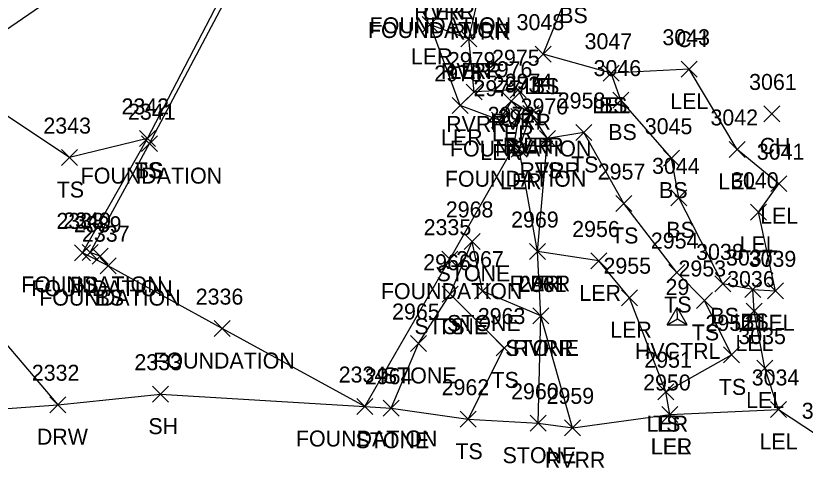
# Model space of a CAD drawing. Extents: x 1512665 to 1513714, y 110636 to 112816.
# Drawn here: x 1513001.7 to 1513100.4, y 110641.4 to 110699.2 of the extents above; entities that cross this region are included whole.
import ezdxf

# ---------------------------------------------------------------- set-up
doc = ezdxf.new("R2010")
doc.units = 0
for name, color, linetype in [('C_A', 7, 'Continuous'), ('C_I', 7, 'Continuous'), ('CPSM', 7, 'Continuous'), ('L_A', 7, 'Continuous'), ('L_I', 7, 'Continuous'), ('L_TIC', 7, 'Continuous'), ('LARO', 7, 'Continuous'), ('LASF', 7, 'Continuous'), ('LAWE', 7, 'Continuous'), ('LBC', 7, 'Continuous'), ('LELB', 7, 'Continuous'), ('LSOGP', 7, 'Continuous'), ('R_A', 7, 'Continuous'), ('R_I', 7, 'Continuous'), ('R_TIC', 7, 'Continuous'), ('RDW', 7, 'Continuous')]:
    doc.layers.add(name, color=color, linetype=linetype)

msp = doc.modelspace()

# ---------------------------------------------------------------- linework, layer by layer
at = {"layer": 'CPSM'}
for p, q in [((1513083.124, 110660.523), (1513084.374, 110662.688)), ((1513085.624, 110660.523), (1513084.374, 110662.688)), ((1513084.375, 110661.244), (1513084.374, 110662.688)), ((1513083.124, 110660.523), (1513084.375, 110661.244)), ((1513084.375, 110661.244), (1513084.375, 110661.244)), ((1513084.375, 110661.244), (1513085.624, 110660.523)), ((1513083.124, 110660.523), (1513085.624, 110660.523))]:
    msp.add_line(p, q, dxfattribs=at)
at = {"layer": 'L_TIC'}
for points in [[(1513052.488, 110697.104), (1513054.488, 110699.104)], [(1513054.488, 110697.104), (1513052.488, 110699.104)], [(1513057.313, 110695.292), (1513059.313, 110697.292)], [(1513059.313, 110695.292), (1513057.313, 110697.292)], [(1513057.313, 110695.292), (1513059.313, 110697.292)], [(1513059.313, 110695.292), (1513057.313, 110697.292)], [(1513066.62, 110693.387), (1513068.62, 110695.387)], [(1513068.62, 110693.387), (1513066.62, 110695.387)], [(1513066.62, 110693.387), (1513068.62, 110695.387)], [(1513068.62, 110693.387), (1513066.62, 110695.387)], [(1513084.847, 110691.498), (1513086.847, 110693.498)], [(1513086.847, 110691.498), (1513084.847, 110693.498)], [(1513075.12, 110690.994), (1513077.12, 110692.994)], [(1513077.12, 110690.994), (1513075.12, 110692.994)], [(1513075.12, 110690.994), (1513077.12, 110692.994)], [(1513077.12, 110690.994), (1513075.12, 110692.994)], [(1513057.96, 110688.646), (1513059.96, 110690.646)], [(1513059.96, 110688.646), (1513057.96, 110690.646)], [(1513063.476, 110688.933), (1513065.476, 110690.933)], [(1513065.476, 110688.933), (1513063.476, 110690.933)], [(1513076.298, 110687.636), (1513078.298, 110689.636)], [(1513078.298, 110687.636), (1513076.298, 110689.636)], [(1513056.248, 110686.974), (1513058.248, 110688.974)], [(1513058.248, 110686.974), (1513056.248, 110688.974)], [(1513062.621, 110687.488), (1513064.621, 110689.488)], [(1513064.621, 110687.488), (1513062.621, 110689.488)], [(1513063.556, 110685.576), (1513065.556, 110687.576)], [(1513065.556, 110685.576), (1513063.556, 110687.576)], [(1513065.06, 110685.938), (1513067.06, 110687.938)], [(1513067.06, 110685.938), (1513065.06, 110687.938)], [(1513065.06, 110685.938), (1513067.06, 110687.938)], [(1513067.06, 110685.938), (1513065.06, 110687.938)], [(1513095.167, 110685.902), (1513097.167, 110687.902)], [(1513097.167, 110685.902), (1513095.167, 110687.902)], [(1513061.15, 110685.123), (1513063.15, 110687.123)], [(1513063.15, 110685.123), (1513061.15, 110687.123)], [(1513071.687, 110683.582), (1513073.687, 110685.582)], [(1513073.687, 110683.582), (1513071.687, 110685.582)], [(1513017.15, 110682.845), (1513019.15, 110684.845)], [(1513019.15, 110682.845), (1513017.15, 110684.845)], [(1513017.15, 110682.845), (1513019.15, 110684.845)], [(1513019.15, 110682.845), (1513017.15, 110684.845)], [(1513067.127, 110682.845), (1513069.127, 110684.845)], [(1513069.127, 110682.845), (1513067.127, 110684.845)], [(1513067.127, 110682.845), (1513069.127, 110684.845)], [(1513069.127, 110682.845), (1513067.127, 110684.845)], [(1513017.401, 110682.181), (1513019.401, 110684.181)], [(1513019.401, 110682.181), (1513017.401, 110684.181)], [(1513062.919, 110681.793), (1513064.919, 110683.793)], [(1513064.919, 110681.793), (1513062.919, 110683.793)], [(1513063.621, 110681.479), (1513065.621, 110683.479)], [(1513065.621, 110681.479), (1513063.621, 110683.479)], [(1513090.854, 110681.46), (1513092.854, 110683.46)], [(1513092.854, 110681.46), (1513090.854, 110683.46)], [(1513007.389, 110680.438), (1513009.389, 110682.438)], [(1513009.389, 110680.438), (1513007.389, 110682.438)], [(1513082.646, 110680.369), (1513084.646, 110682.369)], [(1513084.646, 110680.369), (1513082.646, 110682.369)], [(1513096.083, 110677.175), (1513098.083, 110679.175)], [(1513098.083, 110677.175), (1513096.083, 110679.175)], [(1513076.687, 110674.691), (1513078.687, 110676.691)], [(1513078.687, 110674.691), (1513076.687, 110676.691)], [(1513083.558, 110675.404), (1513085.558, 110677.404)], [(1513085.558, 110675.404), (1513083.558, 110677.404)], [(1513093.517, 110673.6), (1513095.517, 110675.6)], [(1513095.517, 110673.6), (1513093.517, 110675.6)], [(1513057.739, 110669.956), (1513059.739, 110671.956)], [(1513059.739, 110669.956), (1513057.739, 110671.956)], [(1513057.739, 110669.956), (1513059.739, 110671.956)], [(1513059.739, 110669.956), (1513057.739, 110671.956)], [(1513009.024, 110668.518), (1513011.024, 110670.518)], [(1513011.024, 110668.518), (1513009.024, 110670.518)], [(1513009.961, 110668.569), (1513011.961, 110670.569)], [(1513011.961, 110668.569), (1513009.961, 110670.569)], [(1513011.214, 110668.098), (1513013.214, 110670.098)], [(1513013.214, 110668.098), (1513011.214, 110670.098)], [(1513065.91, 110668.682), (1513067.91, 110670.682)], [(1513067.91, 110668.682), (1513065.91, 110670.682)], [(1513065.91, 110668.682), (1513067.91, 110670.682)], [(1513067.91, 110668.682), (1513065.91, 110670.682)], [(1513012.218, 110666.913), (1513014.218, 110668.913)], [(1513014.218, 110666.913), (1513012.218, 110668.913)], [(1513012.218, 110666.913), (1513014.218, 110668.913)], [(1513014.218, 110666.913), (1513012.218, 110668.913)], [(1513054.923, 110667.727), (1513056.923, 110669.727)], [(1513056.923, 110667.727), (1513054.923, 110669.727)], [(1513073.543, 110667.504), (1513075.543, 110669.504)], [(1513075.543, 110667.504), (1513073.543, 110669.504)], [(1513083.328, 110666.051), (1513085.328, 110668.051)], [(1513085.328, 110666.051), (1513083.328, 110668.051)], [(1513089.065, 110664.64), (1513091.065, 110666.64)], [(1513091.065, 110664.64), (1513089.065, 110666.64)], [(1513092.793, 110663.924), (1513094.793, 110665.924)], [(1513094.793, 110663.924), (1513092.793, 110665.924)], [(1513092.793, 110663.924), (1513094.793, 110665.924)], [(1513094.793, 110663.924), (1513092.793, 110665.924)], [(1513054.973, 110663.335), (1513056.973, 110665.335)], [(1513056.973, 110663.335), (1513054.973, 110665.335)], [(1513054.973, 110663.335), (1513056.973, 110665.335)], [(1513056.973, 110663.335), (1513054.973, 110665.335)], [(1513059.041, 110663.737), (1513061.041, 110665.737)], [(1513061.041, 110663.737), (1513059.041, 110665.737)], [(1513077.4, 110662.905), (1513079.4, 110664.905)], [(1513079.4, 110662.905), (1513077.4, 110664.905)], [(1513095.64, 110663.766), (1513097.64, 110665.766)], [(1513097.64, 110663.766), (1513095.64, 110665.766)], [(1513086.78, 110662.565), (1513088.78, 110664.565)], [(1513088.78, 110662.565), (1513086.78, 110664.565)], [(1513092.997, 110661.241), (1513094.997, 110663.241)], [(1513094.997, 110661.241), (1513092.997, 110663.241)], [(1513066.32, 110660.62), (1513068.32, 110662.62)], [(1513068.32, 110660.62), (1513066.32, 110662.62)], [(1513066.32, 110660.62), (1513068.32, 110662.62)], [(1513068.32, 110660.62), (1513066.32, 110662.62)], [(1513026.487, 110659.038), (1513028.487, 110661.038)], [(1513028.487, 110659.038), (1513026.487, 110661.038)], [(1513051.026, 110657.175), (1513053.026, 110659.175)], [(1513053.026, 110657.175), (1513051.026, 110659.175)], [(1513061.741, 110656.612), (1513063.741, 110658.612)], [(1513063.741, 110656.612), (1513061.741, 110658.612)], [(1513090.152, 110655.745), (1513092.152, 110657.745)], [(1513092.152, 110655.745), (1513090.152, 110657.745)], [(1513094.331, 110654.098), (1513096.331, 110656.098)], [(1513096.331, 110654.098), (1513094.331, 110656.098)], [(1513081.939, 110651.144), (1513083.939, 110653.144)], [(1513083.939, 110651.144), (1513081.939, 110653.144)], [(1513081.939, 110651.144), (1513083.939, 110653.144)], [(1513083.939, 110651.144), (1513081.939, 110653.144)], [(1513018.765, 110650.834), (1513020.765, 110652.834)], [(1513020.765, 110650.834), (1513018.765, 110652.834)], [(1513044.304, 110649.287), (1513046.304, 110651.287)], [(1513046.304, 110649.287), (1513044.304, 110651.287)], [(1513044.304, 110649.287), (1513046.304, 110651.287)], [(1513046.304, 110649.287), (1513044.304, 110651.287)], [(1513047.61, 110649.075), (1513049.61, 110651.075)], [(1513049.61, 110649.075), (1513047.61, 110651.075)], [(1513082.446, 110648.297), (1513084.446, 110650.297)], [(1513084.446, 110648.297), (1513082.446, 110650.297)], [(1513082.446, 110648.297), (1513084.446, 110650.297)], [(1513084.446, 110648.297), (1513082.446, 110650.297)], [(1513096.009, 110648.923), (1513098.009, 110650.923)], [(1513098.009, 110648.923), (1513096.009, 110650.923)], [(1513057.22, 110647.703), (1513059.22, 110649.703)], [(1513059.22, 110647.703), (1513057.22, 110649.703)], [(1513065.989, 110647.2), (1513067.989, 110649.2)], [(1513067.989, 110647.2), (1513065.989, 110649.2)], [(1513070.291, 110646.625), (1513072.291, 110648.625)], [(1513072.291, 110646.625), (1513070.291, 110648.625)]]:
    msp.add_lwpolyline(points, dxfattribs=at)
at = {"layer": 'LARO'}
for points in [[(1513083.446, 110649.297), (1513082.939, 110652.144), (1513078.4, 110663.905), (1513074.543, 110668.504), (1513066.91, 110669.682), (1513064.621, 110682.479), (1513066.06, 110686.938), (1513063.621, 110688.488), (1513062.15, 110686.123), (1513057.248, 110687.974), (1513053.488, 110698.104), (1513058.313, 110696.292)], [(1513083.446, 110649.297), (1513097.009, 110649.923), (1513095.331, 110655.098), (1513093.997, 110662.241), (1513093.793, 110664.924), (1513096.64, 110664.766), (1513094.517, 110674.6), (1513097.083, 110678.175), (1513091.854, 110682.46), (1513085.847, 110692.498), (1513076.12, 110691.994), (1513067.62, 110694.387)]]:
    msp.add_lwpolyline(points, dxfattribs=at)
at = {"layer": 'LASF'}
for points in [[(1513048.61, 110650.075), (1513052.026, 110658.175), (1513055.973, 110664.335), (1513058.739, 110670.956)], [(1513066.989, 110648.2), (1513067.32, 110661.62), (1513060.041, 110664.737), (1513058.739, 110670.956)]]:
    msp.add_lwpolyline(points, dxfattribs=at)
at = {"layer": 'LAWE'}
msp.add_lwpolyline([(1513071.291, 110647.625), (1513067.32, 110661.62), (1513066.91, 110669.682), (1513068.127, 110683.845), (1513066.06, 110686.938), (1513064.476, 110689.933), (1513058.96, 110689.646), (1513058.313, 110696.292), (1513059.451, 110701.208), (1513054.984, 110703.704), (1513058.273, 110707.577), (1513062.48, 110710.769), (1513068.993, 110711.091), (1513076.9, 110710.81), (1513081.257, 110711.144), (1513081.642, 110715.191), (1513088.372, 110721.164), (1513089.289, 110728.931), (1513087.702, 110730.166), (1513080.612, 110731.663), (1513081.915, 110745.763)], dxfattribs=at)
at = {"layer": 'LBC'}
for points in [[(1513045.304, 110650.287), (1513027.487, 110660.038), (1513013.218, 110667.913), (1513012.214, 110669.098), (1513010.961, 110669.569), (1513018.401, 110683.181), (1513034.225, 110713.151), (1513039.368, 110710.025), (1513040.959, 110710.138), (1513048.066, 110705.816), (1513054.516, 110701.992), (1513054.311, 110701.401), (1513047.001, 110704.407)], [(1513045.304, 110650.287), (1513055.923, 110668.727), (1513063.919, 110682.793), (1513064.556, 110686.576)]]:
    msp.add_lwpolyline(points, dxfattribs=at)
at = {"layer": 'LELB'}
for points in [[(1513067.62, 110694.387), (1513071.167, 110703.267), (1513073.753, 110708.276), (1513080.884, 110709.446), (1513084.871, 110716.7), (1513089.792, 110721.227), (1513091.693, 110726.726), (1513089.103, 110729.924), (1513082.823, 110732.66), (1513082.971, 110741.966), (1513084.148, 110765.465), (1513082.534, 110771.177), (1513078.618, 110775.838), (1513069.589, 110777.378), (1513065.505, 110782.466)], [(1513018.15, 110683.845), (1513008.389, 110681.438), (1512992.529, 110692.019), (1513011.814, 110705.262), (1513019.652, 110718.711), (1513025.66, 110731.752), (1513034.332, 110738.983), (1513039.854, 110744.651), (1513044.439, 110751.049), (1513044.971, 110754.973), (1513045.977, 110758.546)], [(1513013.218, 110667.913), (1513010.024, 110669.518), (1513018.15, 110683.845), (1513033.901, 110714.169), (1513040.959, 110710.138), (1513040.055, 110717.226), (1513047.05, 110725.671), (1513052.118, 110732.903), (1513052.004, 110737.788), (1513054.843, 110746.139), (1513051.861, 110747.033), (1513047.946, 110747.666), (1513048.845, 110752.609)], [(1513093.793, 110664.924), (1513090.065, 110665.64), (1513084.558, 110676.404), (1513083.646, 110681.369), (1513077.298, 110688.636), (1513076.12, 110691.994)], [(1513082.939, 110652.144), (1513091.152, 110656.745), (1513087.78, 110663.565), (1513084.328, 110667.051), (1513077.687, 110675.691), (1513072.687, 110684.582), (1513068.127, 110683.845)], [(1513058.22, 110648.703), (1513062.741, 110657.612), (1513055.973, 110664.335)]]:
    msp.add_lwpolyline(points, dxfattribs=at)
at = {"layer": 'LSOGP'}
msp.add_lwpolyline([(1512993.751, 110649.547), (1513006.943, 110650.517), (1513019.765, 110651.833), (1513045.304, 110650.288), (1513048.612, 110650.077), (1513058.222, 110648.706), (1513066.99, 110648.202), (1513071.293, 110647.628), (1513083.447, 110649.3), (1513097.008, 110649.92), (1513103.366, 110645.757), (1513111.717, 110641.441), (1513120.026, 110648.442), (1513118.681, 110657.371), (1513118.707, 110659.621), (1513120.883, 110661.498), (1513132.93, 110666.289), (1513145.63, 110674.408), (1513160.629, 110672.862), (1513155.857, 110695.186), (1513155.273, 110725.135), (1513174.532, 110733.791)], dxfattribs=at)
at = {"layer": 'R_TIC'}
for points in [[(1513005.943, 110649.515), (1513007.943, 110651.515)], [(1513007.943, 110649.515), (1513005.943, 110651.515)]]:
    msp.add_lwpolyline(points, dxfattribs=at)
at = {"layer": 'RDW'}
msp.add_lwpolyline([(1512900.459, 110800.085), (1512923.203, 110794.904), (1512935.784, 110783.238), (1512946.819, 110780.951), (1512959.698, 110764.789), (1512961.676, 110750.74), (1512964.35, 110737.826), (1512956.004, 110719.217), (1512960.653, 110706.287), (1512964.16, 110695.737), (1512971.265, 110683.804), (1512977.643, 110679.977), (1512982.193, 110667.902), (1512995.78, 110663.608), (1513006.943, 110650.515)], dxfattribs=at)

# ---------------------------------------------------------------- texts
at = {"layer": 'C_A'}
msp.add_text('HVCTRL', height=2, dxfattribs=at).set_placement((1513079.067, 110656.244))
at = {"layer": 'C_I'}
msp.add_text('29', height=2, dxfattribs=at).set_placement((1513082.902, 110664.244))
at = {"layer": 'L_A'}
for s, p in [('RVRR', (1513051.495, 110698.704)), ('LER', (1513052.566, 110698.704)), ('BS', (1513069.608, 110698.267)), ('FOUNDATION', (1513045.705, 110696.401)), ('FOUNDATION', (1513045.91, 110696.992)), ('RVRR', (1513055.963, 110696.208)), ('CH', (1513084.237, 110695.266)), ('LER', (1513051.071, 110693.104)), ('RVRR', (1513054.824, 110691.292)), ('LER', (1513055.895, 110691.292)), ('LEL', (1513065.258, 110689.387)), ('BS', (1513066.061, 110689.387)), ('LEL', (1513083.485, 110687.498)), ('LEL', (1513073.758, 110686.994)), ('BS', (1513074.561, 110686.994)), ('RVRR', (1513055.472, 110684.646)), ('RVRR', (1513060.988, 110684.933)), ('BS', (1513075.739, 110683.636)), ('LER', (1513054.831, 110682.974)), ('LER', (1513061.204, 110683.488)), ('FOUNDATION', (1513055.95, 110681.576)), ('RVRR', (1513062.571, 110681.938)), ('LER', (1513063.642, 110681.938)), ('CH', (1513094.655, 110681.902)), ('LER', (1513059.733, 110681.123)), ('TS', (1513071.096, 110679.582)), ('TS', (1513016.559, 110678.845)), ('BS', (1513016.591, 110678.845)), ('RVRR', (1513064.639, 110678.845)), ('TS', (1513066.537, 110678.845)), ('FOUNDATION', (1513009.795, 110678.181)), ('FOUNDATION', (1513055.313, 110677.793)), ('LER', (1513062.204, 110677.479)), ('LEL', (1513089.492, 110677.46)), ('TS', (1513006.798, 110676.438)), ('BS', (1513082.087, 110676.369)), ('LEL', (1513094.721, 110673.175)), ('TS', (1513076.097, 110670.691)), ('BS', (1513082.999, 110671.404)), ('LEL', (1513092.155, 110669.6)), ('STONE', (1513054.282, 110665.956)), ('STONE', (1513054.282, 110665.956)), ('FOUNDATION', (1513002.355, 110664.569)), ('FOUNDATION', (1513003.608, 110664.098)), ('BS', (1513008.465, 110664.518)), ('RVRR', (1513063.422, 110664.682)), ('LER', (1513064.493, 110664.682)), ('FOUNDATION', (1513004.612, 110662.913)), ('BS', (1513011.659, 110662.913)), ('FOUNDATION', (1513047.317, 110663.727)), ('LER', (1513072.125, 110663.504)), ('TS', (1513082.737, 110662.051)), ('BS', (1513088.506, 110660.64)), ('LEL', (1513091.431, 110659.924)), ('BS', (1513092.234, 110659.924)), ('STONE', (1513051.517, 110659.335)), ('TS', (1513054.383, 110659.335)), ('STONE', (1513055.584, 110659.737)), ('LER', (1513075.983, 110658.905)), ('LEL', (1513094.278, 110659.766)), ('TS', (1513086.189, 110658.565)), ('LEL', (1513091.635, 110657.241)), ('STONE', (1513062.863, 110656.62)), ('RVRR', (1513063.832, 110656.62)), ('FOUNDATION', (1513018.88, 110655.038)), ('STONE', (1513047.569, 110653.175)), ('TS', (1513061.15, 110652.612)), ('TS', (1513089.561, 110651.745)), ('LEL', (1513092.968, 110650.098)), ('LER', (1513080.522, 110647.144)), ('TS', (1513081.349, 110647.144)), ('SH', (1513018.253, 110646.834)), ('FOUNDATION', (1513036.698, 110645.287)), ('FOUNDATION', (1513036.698, 110645.287)), ('STONE', (1513044.153, 110645.075)), ('LER', (1513081.029, 110644.297)), ('LEL', (1513081.084, 110644.297)), ('LEL', (1513094.646, 110644.923)), ('TS', (1513056.63, 110643.703)), ('STONE', (1513062.532, 110643.2)), ('RVRR', (1513067.803, 110642.625))]:
    msp.add_text(s, height=2, dxfattribs=at).set_placement(p)
at = {"layer": 'L_I'}
for s, p in [('3048', (1513064.281, 110697.387)), ('3048', (1513064.281, 110697.387)), ('3043', (1513082.509, 110695.498)), ('3047', (1513072.781, 110694.994)), ('3047', (1513072.781, 110694.994)), ('2979', (1513055.692, 110692.646)), ('2975', (1513061.216, 110692.933)), ('2976', (1513060.306, 110691.488)), ('3046', (1513073.904, 110691.636)), ('2978', (1513053.988, 110690.974)), ('2973', (1513061.296, 110689.576)), ('2974', (1513062.8, 110689.938)), ('2974', (1513062.8, 110689.938)), ('3061', (1513093.348, 110689.902)), ('2977', (1513058.89, 110689.123)), ('2958', (1513069.427, 110687.582)), ('2342', (1513014.89, 110686.845)), ('2342', (1513014.89, 110686.845)), ('2970', (1513064.781, 110686.845)), ('2970', (1513064.781, 110686.845)), ('2341', (1513015.708, 110686.181)), ('2972', (1513060.659, 110685.793)), ('2971', (1513061.928, 110685.479)), ('3042', (1513088.516, 110685.46)), ('2343', (1513005.129, 110684.438)), ('3045', (1513080.307, 110684.369)), ('3041', (1513094.312, 110681.175)), ('2957', (1513074.427, 110678.691)), ('3044', (1513081.219, 110679.404)), ('3040', (1513091.092, 110677.6)), ('2968', (1513055.431, 110673.956)), ('2968', (1513055.431, 110673.956)), ('2969', (1513063.595, 110672.682)), ('2969', (1513063.595, 110672.682)), ('2338', (1513006.764, 110672.518)), ('2340', (1513007.615, 110672.569)), ('2339', (1513008.946, 110672.098)), ('2335', (1513052.663, 110671.727)), ('2337', (1513009.958, 110670.913)), ('2337', (1513009.958, 110670.913)), ('2956', (1513071.228, 110671.504)), ('2954', (1513081.068, 110670.051)), ('2967', (1513056.734, 110667.737)), ('3038', (1513086.726, 110668.64)), ('3037', (1513090.454, 110667.924)), ('3037', (1513090.454, 110667.924)), ('3039', (1513093.294, 110667.766)), ('2966', (1513052.611, 110667.335)), ('2966', (1513052.611, 110667.335)), ('2955', (1513075.14, 110666.905)), ('2953', (1513084.52, 110666.565)), ('3036', (1513090.603, 110665.241)), ('2961', (1513064.58, 110664.62)), ('2961', (1513064.58, 110664.62)), ('2336', (1513024.172, 110663.038)), ('2965', (1513048.719, 110661.175)), ('2963', (1513059.434, 110660.612)), ('2952', (1513087.892, 110659.745)), ('3035', (1513091.992, 110658.098)), ('2951', (1513080.246, 110655.144)), ('2951', (1513080.246, 110655.144)), ('2333', (1513016.505, 110654.834)), ('2334', (1513042.044, 110653.287)), ('2334', (1513042.044, 110653.287)), ('2964', (1513045.303, 110653.075)), ('3034', (1513093.67, 110652.923)), ('2950', (1513080.1, 110652.297)), ('2950', (1513080.1, 110652.297)), ('2962', (1513054.913, 110651.703)), ('2960', (1513063.595, 110651.2)), ('2959', (1513068.024, 110650.625)), ('3066', (1513099.926, 110648.76))]:
    msp.add_text(s, height=2, dxfattribs=at).set_placement(p)
at = {"layer": 'R_A'}
msp.add_text('DRW', height=2, dxfattribs=at).set_placement((1513004.313, 110645.515))
at = {"layer": 'R_I'}
msp.add_text('2332', height=2, dxfattribs=at).set_placement((1513003.683, 110653.515))

doc.saveas('drawing.dxf')
